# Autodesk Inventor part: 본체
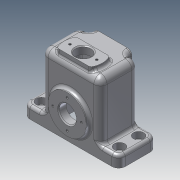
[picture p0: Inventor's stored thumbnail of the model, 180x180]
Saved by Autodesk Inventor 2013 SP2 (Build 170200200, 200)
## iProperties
Created: 2023-12
Part Number: 본체
Material: 알루미늄 6061
Document SubType Name: Modeling
Designer: i
Density: 2.71 g/cm^3
Mass: 220.305 g
Surface Area: 358.61 cm^2
Volume: 81.2934 cm^3
Author: i
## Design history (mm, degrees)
sketch "스케치1"
  geometry: L1 (-31, 20)-(31, 20); L2 (31, 20)-(31, -20); L3 (31, -20)-(-31, -20); L4 (-31, -20)-(-31, 20); L5 (-31, 20)-(31, -20); L6 (31, 20)-(-31, -20); 1 further point
  constraints: 12 end point, 2 midpoint, 2 parallel, 1 horizontal, 1 perpendicular
  dimensions: "d0" = 62 distance of L2.end L3.end; "d1" = 40 distance of L1.end L2.end
extrude "돌출1" new body sketch "스케치1" distance "d2" = 72; taper "d3" = 0 deg
feature "쉘1" dims "d4" = 4
sketch "스케치2"
  geometry: L1 (62, 0)-(0, 0) reference; C1 r 20 at (31, 28); 2 further points
  constraints: 1 centre point, 1 midpoint, 1 vertical alignment
  dimensions: "d5" = 40 diameter of C1; "d6" = 28 distance from line of L1 C1.centre
extrude "돌출2" join sketch "스케치2" distance "d7" = 4; taper "d8" = 0 deg
sketch "스케치3"
  geometry: L1 (62, 0)-(0, 0) reference; C1 r 12 at (31, 28); 2 further points
  constraints: 1 centre point, 1 midpoint, 1 vertical alignment
  dimensions: "d9" = 24 diameter of C1; "d10" = 28 distance from line of L1 C1.centre
extrude "돌출3" join sketch "스케치3" distance "d11" = 4; taper "d12" = 0 deg
sketch "스케치4"
  geometry: L1 (62, 0)-(0, 0) reference; L2 (0, 72)-(62, 72) reference; L3 (11, 72)-(51, 72); L4 (51, 72)-(51, 48); L5 (51, 48)-(11, 48); L6 (11, 48)-(11, 72); 3 further points
  constraints: 8 end point, 3 midpoint, 2 parallel, 1 horizontal, 1 perpendicular, 1 vertical alignment
  dimensions: "d13" = 40 distance of L4.end L5.end; "d15" = 24 distance of L5.end L3.start
extrude "돌출4" join sketch "스케치4" distance "d16" = 4; taper "d17" = 0 deg
sketch "스케치5"
  geometry: L1 (31, 20)-(-31, 20) reference; L2 (-31, 20)-(-31, -20) reference; L3 (-31, -20)-(31, -20) reference; L4 (31, -20)-(31, 20) reference; L5 (50, 20)-(-50, 20); L6 (-50, 20)-(-50, -20); L7 (-50, -20)-(50, -20); L8 (50, -20)-(50, 20); L9 (50, 20)-(-50, -20); L10 (-50, 20)-(50, -20); 1 further point
  constraints: 12 end point, 2 midpoint, 2 parallel, 1 horizontal, 1 perpendicular
  dimensions: "d18" = 100 distance of L7.end L6.end; "d19" = 40 distance of L6.end L5.end
extrude "돌출5" join sketch "스케치5" distance "d20" = 12; taper "d21" = 0 deg
sketch "스케치6"
  geometry: L1 (-31, -20)-(31, -20) reference; L2 (-20, 24)-(20, 24) reference; L3 (-20, -17)-(-17.321, -17); L4 (20, -17)-(20, 3); L5 (20, 3)-(17.321, 3); L6 (-20, 3)-(-20, -17); L7 (-20, -7)-(20, -7); L8 (17.321, 3)-(-17.321, 3); L9 (17.321, -17)-(20, -17); L10 (-17.321, -17)-(17.321, -17); L11 (-17.321, 3)-(-20, 3); A1 r 20 centre (0, -7) between (-17.321, 3) and (-17.321, -17); A2 r 20 centre (0, -7) between (17.321, 3) and (-17.321, 3); A3 r 20 centre (0, -7) between (15.199, -20) and (17.321, 3); A4 r 20 centre (0, -7) between (-17.321, -17) and (15.199, -20); 2 further points
  constraints: 18 end point, 10 parallel, 9 point on circle, 4 centre point, 3 horizontal, 3 midpoint, 3 perpendicular, 2 point on line, 1 coincident, 1 vertical alignment
  dimensions: "d22" = 31 distance from line of L2 L7.start; "d23" = 20 distance of L6.start L3.start; "d24" = 40 diameter of A1; "d25" = 40 distance of L4.end L6.start
extrude "돌출6" join sketch "스케치6" distance "d26" = 4; taper "d27" = 0 deg
sketch "스케치7"
  geometry: C1 r 8 at (0, -7); A1 r 20 centre (0, -7) between (-17.321, 3) and (-17.321, -17) reference; 1 further point
  constraints: 1 centre point, 1 coincident
  dimensions: "d28" = 16 diameter of C1
extrude "돌출7" cut sketch "스케치7" stored distance "d29" = 4; taper "d30" = 0 deg
sketch "스케치8"
  geometry: C1 r 12 at (0, 0) reference; 2 further points
  constraints: 1 coincident
hole "구멍1" sketch "스케치8" at (0, 0) diameter "d31" = 14.917; stored, may be unused: countersink angle "d35" = 90 deg, drill point angle "d37" = 0 deg; dims "d32" = 6, "d33" = 4, "d34" = 2, "d36" = 8
sketch "스케치9"
  geometry: C1 r 20 at (0, 0) reference; 2 further points
  constraints: 1 coincident
hole "구멍2" sketch "스케치9" at (0, 0) diameter "d38" = 18; stored, may be unused: countersink angle "d42" = 90 deg, drill point angle "d44" = 0 deg; dims "d39" = 6, "d40" = 4, "d41" = 2, "d43" = 8
sketch "스케치10"
  geometry: C1 r 8 at (0, -7) reference; 3 further points
  constraints: 2 horizontal alignment
  dimensions: "d45" = 28 distance of point (-14, -7) point (14, -7); "d47" = 14 distance of C1.centre point (-14, -7)
hole "구멍3" sketch "스케치10" at (-14, -7), (14, -7) diameter "d48" = 2.459; stored, may be unused: countersink angle "d52" = 90 deg, drill point angle "d54" = 0 deg; dims "d49" = 6, "d50" = 4, "d51" = 2, "d53" = 8
sketch "스케치11"
  geometry: L1 (51, 72)-(11, 72) reference; 3 further points
  constraints: 1 horizontal alignment
  dimensions: "d55" = 6 distance from line of point (17, 66) L1; "d56" = 28 distance of point (45, 66) point (17, 66); "d57" = 14 horizontal distance of point (31, 0) point (17, 66)
hole "구멍4" sketch "스케치11" at (17, 66), (45, 66) diameter "d58" = 2.459; stored, may be unused: countersink angle "d62" = 90 deg, drill point angle "d64" = 0 deg; dims "d59" = 6, "d60" = 4, "d61" = 2, "d63" = 8
sketch "스케치12" dims "d65" = 30
  geometry: C1 r 9 at (0, 0) reference; C2 r 20 at (0, 0) reference; 3 further points
  constraints: 2 vertical alignment, 1 coincident, 2 other
hole "구멍5" sketch "스케치12" at (0, 15) diameter "d66" = 2.459; stored, may be unused: countersink angle "d70" = 90 deg, drill point angle "d72" = 0 deg; dims "d67" = 6, "d68" = 4, "d69" = 2, "d71" = 8
chamfer "모따기1" distance "d88" = 1; stored, may be unused: second distance "d89" = 2, angle "d90" = 45 deg
fillet "모깎기8" dims "d93" = 7
fillet "모깎기9" dims "d94" = 3
fillet "모깎기10" dims "d95" = 7
fillet "모깎기11" dims "d96" = 3
fillet "모깎기15" dims "d100" = 7
fillet "모깎기16" dims "d101" = 3
fillet "모깎기17" dims "d102" = 7
fillet "모깎기23" dims "d108" = 5
fillet "모깎기19" dims "d104" = 3
fillet "모깎기20" dims "d105" = 3
fillet "모깎기21" dims "d106" = 3
fillet "모깎기22" dims "d107" = 5
fillet "모깎기24" dims "d109" = 3
fillet "모깎기25" dims "d110" = 3
fillet "모깎기26" dims "d111" = 3
sketch "스케치14"
  geometry: L1 (26, -15)-(0, -15) reference; L2 (-11, 25)-(-11, 1) reference; 2 further points
  constraints: 1 other
  dimensions: "d112" = 40 distance from line of L1 point (12, 25); "d113" = 23 distance from line of L2 point (12, 25)
feature "엠보싱1" sketch "스케치14" dims "d114" = 0.5, "d115" = 0
fillet "모깎기27" dims "d116" = 3
sketch "스케치15"
  geometry: L1 (33.165, 17)-(43, 17) reference; L2 (34, -13)-(34, 13) reference; L3 (43, -17)-(33.165, -17) reference; L4 (47, 13)-(47, -13) reference; L5 (-43, -20)-(-33.165, -20) reference; A1 r 10 centre (24, 13) between (34, 13) and (33.165, 17) reference; A2 r 10 centre (24, -13) between (33.165, -17) and (34, -13) reference; A3 r 4 centre (43, -13) between (43, -17) and (47, -13) reference; A4 r 4 centre (43, 13) between (47, 13) and (43, 17) reference; 5 further points
  constraints: 2 horizontal alignment, 2 vertical alignment
  dimensions: "d117" = 82 distance of point (41, 10) point (-41, 10); "d119" = 20 distance of point (-41, -10) point (-41, 10); "d120" = 10 distance from line of L5 point (-41, -10); "d121" = 41 horizontal distance of point (0, 0) point (-41, 10)
hole "구멍7" sketch "스케치15" at (-41, 10), (-41, -10), (41, 10), (41, -10) diameter "d122" = 6.6; stored, may be unused: countersink angle "d126" = 90 deg, drill point angle "d128" = 0 deg; dims "d123" = 6, "d124" = 11, "d125" = 6.6, "d127" = 8
node "솔리드1"
pattern_circular "원형 패턴1" dims angle "d74" = 360 deg
node "투영된 루프2"
